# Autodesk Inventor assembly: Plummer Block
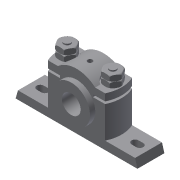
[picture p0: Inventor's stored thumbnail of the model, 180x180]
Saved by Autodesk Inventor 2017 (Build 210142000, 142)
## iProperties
Created: 2011-07
Part Number: Plummer Block
Document SubType Name: Assembly
Designer: CadCim
Author: CadCim
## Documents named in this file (7)
- D:\KAVITA\Autodesk Inventor_ 2016 Project_Kavita\Inventor_Part Files\Inventor_2016_Part\c11_Inv_2016\c11_inv_2016_prt\fig 11-40 through 11-45\Plummer Block.iam
- D:\KAVITA\Autodesk Inventor_ 2016 Project_Kavita\Inventor_Part Files\Inventor_2016_Part\c11_Inv_2016\c11_inv_2016_prt\fig 11-40 through 11-45\Casting.ipt
- D:\KAVITA\Autodesk Inventor_ 2016 Project_Kavita\Inventor_Part Files\Inventor_2016_Part\c11_Inv_2016\c11_inv_2016_prt\fig 11-40 through 11-45\Brasses.ipt
- D:\KAVITA\Autodesk Inventor_ 2016 Project_Kavita\Inventor_Part Files\Inventor_2016_Part\c11_Inv_2016\c11_inv_2016_prt\fig 11-40 through 11-45\Cap.ipt
- D:\KAVITA\Autodesk Inventor_ 2016 Project_Kavita\Inventor_Part Files\Inventor_2016_Part\c11_Inv_2016\c11_inv_2016_prt\fig 11-40 through 11-45\Bolt.ipt
- D:\KAVITA\Autodesk Inventor_ 2016 Project_Kavita\Inventor_Part Files\Inventor_2016_Part\c11_Inv_2016\c11_inv_2016_prt\fig 11-40 through 11-45\Nut.ipt
- D:\KAVITA\Autodesk Inventor_ 2016 Project_Kavita\Inventor_Part Files\Inventor_2016_Part\c11_Inv_2016\c11_inv_2016_prt\fig 11-40 through 11-45\Lock Nut.ipt
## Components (9 placed, 6 different names)
1. Casting:1 — Mate:1, Mate:2, Insert:1, Insert:2, Angle:1, Angle:2
2. Brasses:1 — Mate:1, Mate:2, Mate:3, Mate:4
3. Cap:1 — Mate:3, Mate:4, Insert:3, Insert:4
4. Bolt:1 — Insert:1, Angle:1
5. Bolt:2 — Insert:2, Angle:2
6. Nut:1 — Insert:3, Insert:6
7. Nut:2 — Insert:4, Insert:5
8. Lock Nut:1 — Insert:6
9. Lock Nut:2 — Insert:5
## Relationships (12: Insert 6, Mate 4, Angle 2)
- Mate:1: Casting:1 ↔ Brasses:1
- Mate:2: Casting:1 ↔ Brasses:1
- Mate:3: Brasses:1 ↔ Cap:1
- Mate:4: Brasses:1 ↔ Cap:1
- Insert:1: Casting:1 ↔ Bolt:1
- Insert:2: Casting:1 ↔ Bolt:2
- Angle:1: Casting:1 ↔ Bolt:1
- Angle:2: Casting:1 ↔ Bolt:2
- Insert:3: Cap:1 ↔ Nut:1
- Insert:4: Cap:1 ↔ Nut:2
- Insert:5: Nut:2 ↔ Lock Nut:2
- Insert:6: Nut:1 ↔ Lock Nut:1
